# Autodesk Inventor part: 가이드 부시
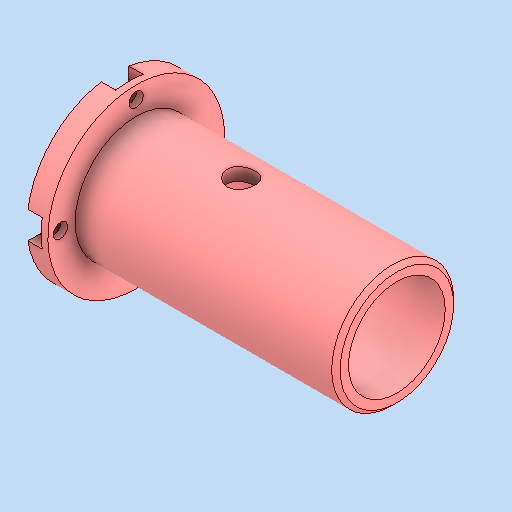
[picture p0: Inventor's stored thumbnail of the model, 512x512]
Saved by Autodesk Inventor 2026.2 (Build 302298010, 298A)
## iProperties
Created: 2026-08
Part Number: 가이드 부시
Material: 강철, 탄소
Document SubType Name: Modeling
Designer: PC2-02
Density: 7.85 g/cm^3
Appearance: 기본값
Author: jhkim
Sending System: Autodesk Inventor 2027
Preprocessor: ST-DEVELOPER v20.1
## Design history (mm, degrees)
feature "솔리드1"
node "솔리드2"
